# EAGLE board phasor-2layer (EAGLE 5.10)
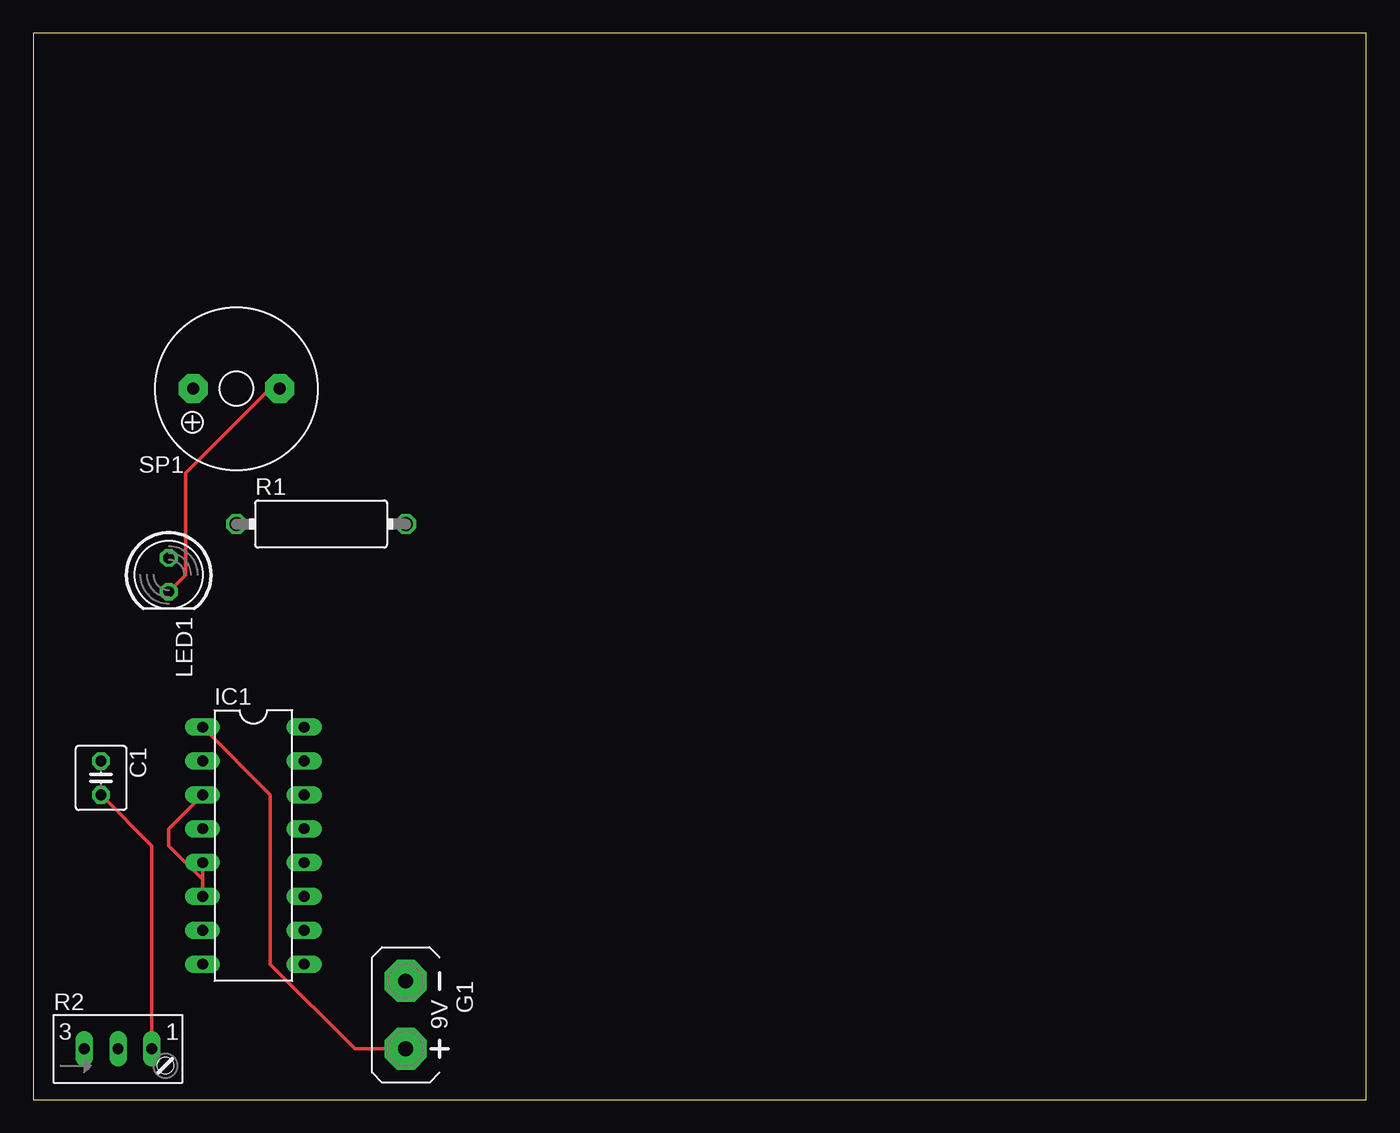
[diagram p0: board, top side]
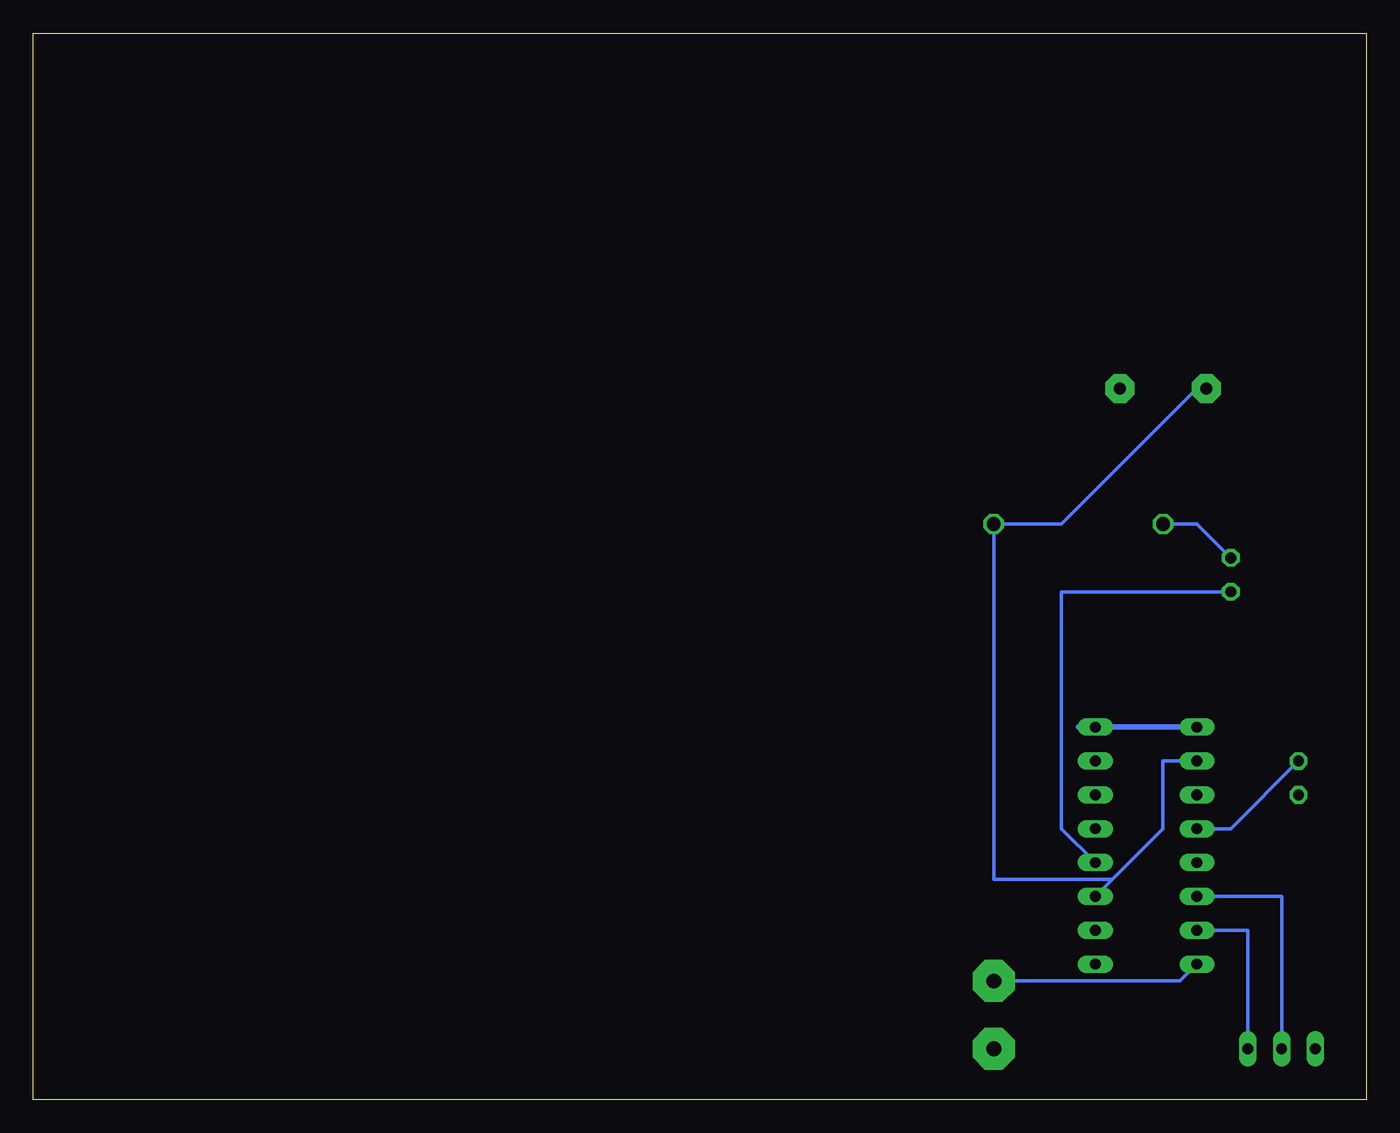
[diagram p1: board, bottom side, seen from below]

Size 100 x 80 mm. Coordinates in mm from the lower left corner, seen from the top.
Outline: 0,0 100,0 100,80 0,80 0,0
Copper layers (1*16): Top 0.035mm / dielectric 1.5mm / Bottom 0.035mm
Design rules "default": minimum track width 10mil, minimum drill 24mil, track to track 8mil, track to pad 8mil, pad to pad 8mil, via to via 8mil, smd to smd 8mil, copper to edge 40mil, drill to drill 8mil, minimum pad ring 10mil, minimum via ring 8mil, stop-mask expansion 4mil, vias tented up to drill 0mil, thermal gap 10mil

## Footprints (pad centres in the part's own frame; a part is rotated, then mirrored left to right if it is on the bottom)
C025-040X050 = drill 0.813 octagon: 1 -1.27,0; 2 1.27,0
AB9V = drill 1.118 pad 3.15 octagon: + 0,2.54; - 0,-2.54
DIL16 = drill 0.813 long: 1 -8.89,-3.81; 2 -6.35,-3.81; 3 -3.81,-3.81; 4 -1.27,-3.81; 5 1.27,-3.81; 6 3.81,-3.81; 7 6.35,-3.81; 8 8.89,-3.81; 9 8.89,3.81; 10 6.35,3.81; 11 3.81,3.81; 12 1.27,3.81; 13 -1.27,3.81; 14 -3.81,3.81; 15 -6.35,3.81; 16 -8.89,3.81
LED5MM = drill 0.813 octagon: A -1.27,0; K 1.27,0
V234/12 = drill 1.016 octagon: 1 -6.35,0; 2 6.35,0
S64W = drill 0.813 long: A 2.54,1.27; E -2.54,1.27; S 0,1.27
KSS1201 = drill 0.914 pad 2.159 octagon: + 3.251,0; - -3.251,0

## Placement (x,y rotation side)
C1  [C025-040X050]  5.08,24.13 270 top
G1  AB9V  [AB9V]  27.94,6.35 180 top
IC1  4049N  [DIL16]  16.51,19.05 270 top
LED1  [LED5MM]  10.16,39.37 270 top
R1  [V234/12]  21.59,43.18 0 top
R2  [S64W]  6.35,2.54 0 top
SP1  KSS1201  [KSS1201]  15.24,53.34 180 top

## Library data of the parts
C1 = resistor
G1 = battery
IC1 = 40xx
LED1 = led
R1 = resistor; R1: 2200
R2 = pot; POT: 1000000
SP1 = buzzer

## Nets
N$1: IC1.2 IC1.11 R1.2 SP1.+
N$2: LED1.A R1.1
N$3: IC1.12 LED1.K SP1.-
N$4: C1.1 IC1.4
N$5: C1.2 IC1.7 R2.A
N$6: IC1.3 IC1.5 IC1.6 R2.S
N$7: G1.- IC1.8
N$8: G1.+ IC1.1

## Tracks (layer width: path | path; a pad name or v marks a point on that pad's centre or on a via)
N$1
  Bottom 0.254: 19.05,16.51 15.24,20.32 15.24,25.4 IC1.2 | 19.05,16.51 IC1.11 | 19.05,16.51 27.94,16.51 R1.2 22.86,43.18 12.7,53.34 SP1.+
N$2
  Bottom 0.254: LED1.A 12.7,43.18 R1.1
N$3
  Top 0.254: LED1.K 11.43,39.37 11.43,46.99 17.78,53.34 SP1.-
  Bottom 0.254: IC1.12 22.86,20.32 22.86,38.1 LED1.K
N$4
  Bottom 0.254: C1.1 10.16,20.32 IC1.4
N$5
  Top 0.254: C1.2 8.89,19.05 R2.A
  Bottom 0.254: R2.A 8.89,12.7 IC1.7
N$6
  Top 0.254: IC1.6 12.7,16.51 | 12.7,16.51 IC1.5 | IC1.3 10.16,20.32 10.16,19.05 12.7,16.51
  Bottom 0.254: R2.S 6.35,15.24 IC1.6
N$7
  Bottom 0.254: IC1.8 13.97,8.89 G1.-
N$8
  Top 0.254: IC1.1 17.78,22.86 17.78,10.16 24.13,3.81 G1.+
  Bottom 0.406: IC1.1 21.59,27.94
